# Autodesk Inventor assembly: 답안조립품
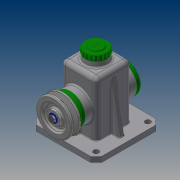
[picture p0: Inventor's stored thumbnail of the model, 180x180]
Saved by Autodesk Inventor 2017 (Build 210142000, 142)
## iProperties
Part Number: 답안조립품
Material: 일반
Document SubType Name: Assembly
Designer: 20
Author: 20
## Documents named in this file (14)
- C:\Users\20\Desktop\470818V1016\답안조립품.iam
- C:\Users\20\Desktop\470818V1016\본체1.ipt
- C:\Users\20\Desktop\470818V1016\상부캡.ipt
- C:\Users\20\Desktop\470818V1016\앞커버.ipt
- C:\Users\20\Desktop\470818V1016\뒤커버.ipt
- C:\Users\20\Desktop\470818V1016\오일실 15 25 7.ipt
- C:\Users\20\Desktop\470818V1016\베어링 15 x 35 x 11.ipt
- C:\Users\20\Desktop\470818V1016\축.ipt
- C:\Users\20\Desktop\470818V1016\키 5 x 5 x 14.ipt
- C:\Users\20\Desktop\470818V1016\V-벨트풀리.ipt
- C:\Users\20\Desktop\470818V1016\와셔.ipt
- C:\Users\20\Desktop\470818V1016\멈춤링 15 x 1.ipt
- C:\Users\20\Desktop\470818V1016\볼트 M6 x 12.ipt
- C:\Users\20\Desktop\470818V1016\볼트 M4 x 10.ipt
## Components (1 placed, 1 different names)
1. V-벨트풀리:1
